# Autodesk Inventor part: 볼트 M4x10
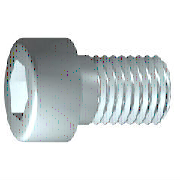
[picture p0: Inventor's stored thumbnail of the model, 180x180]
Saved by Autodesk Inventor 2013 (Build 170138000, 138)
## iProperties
IsCustomPart: 1
Created: 2012-02
Part Number: 볼트 M4x10
Material: 스테인리스강
Description: 6각 소켓 머리 캡 나사
Document SubType Name: Modeling
Standard: ISO 4762
Designer: mduedu
Standard Revision: Fourth edition 2004-03-01
Standards Organization: ISO
Language: ko-KR
Size Designation: M4 x 10
Categories: <MemberInstance><Categories><Category DisplayName="조임쇠" InternalName="e4da775c-781d-43d5-af7c-5136215cf5a6" Mnemonic="FSTN"><Category DisplayName="볼트" InternalN
Density: 7.75 g/cm^3
Author: mduedu
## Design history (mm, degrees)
sketch "스케치1"
  geometry: L1 (-1, 0)-(10, 0); L2 (10, 0)-(10, 2); L3 (10, 2)-(1.75, 2); L4 (1.75, 2)-(1.32, 2); L5 (1.32, 2)-(0, 2); L6 (0, 2)-(0, 3.5); L7 (0, 3.5)-(-4, 3.5); L8 (-4, 3.5)-(-4, 1.732); L9 (-4, 1.732)-(-2, 1.732); L10 (-2, 1.732)-(-1, 0); L11 (-6.8, 0)-(12.8, 0) reference; L12 (0, -0.7)-(0, 4.2) reference; L13 (1.75, 2)-(0, 2)
  constraints: 22 end point, 6 parallel, 2 collinear, 2 perpendicular, 1 horizontal, 1 point on line
  dimensions: "d1" = 8.25 distance from line of L3.end L2 (= GEL); "d2" = 0.42952 distance of L4.end L3.end (computed from GAL); "d3" = 4 distance between parallel lines of L8 L6 (= KOH); "d4" = 2 distance of L8.end L9.end (= INTI); "d5" = 60 deg angle of L10 L1; "d6" = 4 diameter of L3 L1 (= GD); "d7" = 4 diameter of L5 L1 (= BDM); "d8" = 3.4641 diameter of L9 L1 (= 1.1547 x SW); "d9" = 7 diameter of L7 L1 (= KOD); "d26" = 10 distance between parallel lines of L12 L2 (= NLG)
revolve "본체" sketch "스케치1" stored, may be unused: angle "d10" = 90 deg
sketch "스케치2"
  geometry: L1 (0, -4.9)-(0, 4.9) reference; L2 (-4.9, 0)-(4.9, 0) reference; L3 (1.732, 0)-(0.866, -1.5); L4 (0.866, -1.5)-(-0.866, -1.5); L5 (-0.866, -1.5)-(-1.732, 0); L6 (-1.732, 0)-(-0.866, 1.5); L7 (-0.866, 1.5)-(0.866, 1.5); L8 (0.866, 1.5)-(1.732, 0); 2 further points
  constraints: 12 end point, 1 coincident, 1 horizontal alignment, 1 point on line, 12 other
extrude "슬롯" join sketch "스케치2" stored distance "d11" = 10; taper "d12" = 0 deg
workplane "Work Plane1"
body "Solid1"
fillet "모깎기1" dims "d17" = 0.4 (= RR)
feature "스레드" dims "d13" = 8.25 (= GEL), "d14" = 0
chamfer "모따기1" distance "d15" = 0.42941 (= -0.5 x SPD + 0.5 x GD); stored, may be unused: second distance "d16" = 0.42941 (= GUL), angle "d27" = 45 deg
other parameters: "GD" = 4 [user parameter; used in 2 equation terms], "NLG" = 10 [user parameter; used in 1 equation term], "GEL" = 8.25 [user parameter; used in 2 equation terms], "KOD" = 7 [user parameter; used in 1 equation term], "KOH" = 4 [user parameter; used in 1 equation term], "INTI" = 2 [user parameter; used in 1 equation term], "GAL" = 0.42941 (= 0.61345 x PTC) [user parameter; used in 1 equation term], "GUL" = 0.42941 (= 0.61345 x PTC) [user parameter; used in 1 equation term], "BDM" = 4 (= NND) [user parameter; used in 1 equation term], "SW" = 3 [user parameter; used in 2 equation terms], "RR" = 0.4 [user parameter; used in 1 equation term], "SPD" = 3.14117 (= NND - 1.2269 x PTC) [user parameter; used in 1 equation term], "d19" = 0, "d28" = 0, "d29" = 0, "R" = 0.1 [user parameter], "TOA" = 30 deg [user parameter], "GD1" = 3.14117 (= THREADDIA - 1.2269 x PTC) [user parameter], "THREADDIA" = 4 [user parameter; used in 1 equation term], "FAWI" = 45 deg [user parameter], "TPU" = 14.28571 (computed from PTC) [user parameter], "PTC" = 0.7 [user parameter; used in 5 equation terms], "NND" = 4 [user parameter; used in 2 equation terms], "E0" = 3.465 (= 1.155 x SW) [user parameter]
